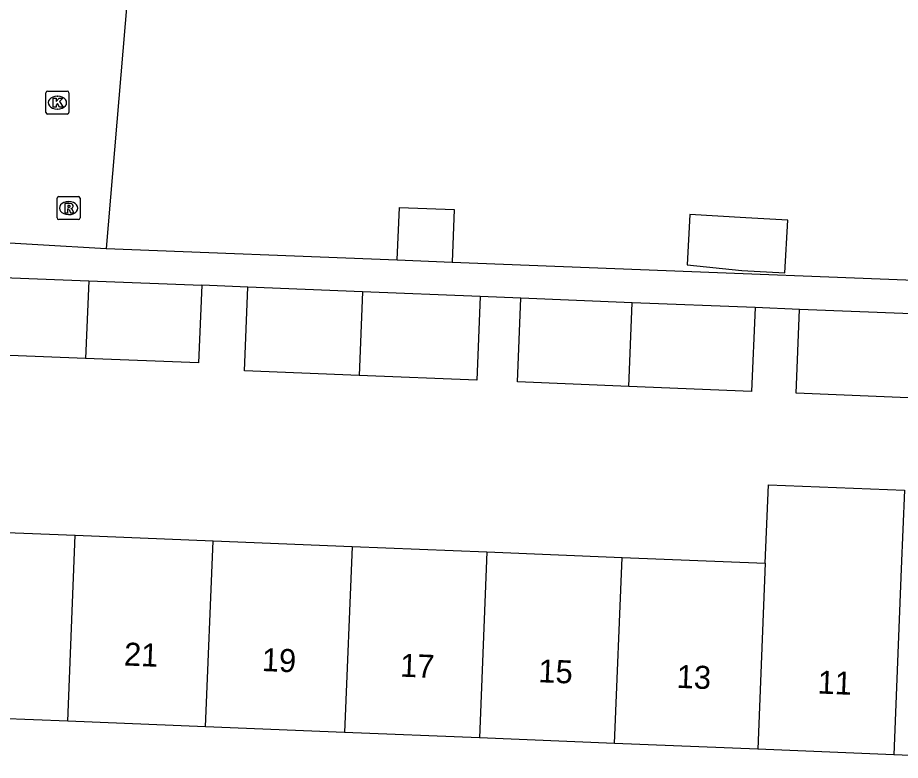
# Model space of a CAD drawing. Extents: x 161355 to 162026, y 386504 to 387459.
# Drawn here: x 161432.85 to 161471.21, y 386887.06 to 386919.31 of the extents above; entities that cross this region are included whole.
import ezdxf

# ---------------------------------------------------------------- set-up
doc = ezdxf.new("R2010")
doc.units = 0
for name, color, linetype in [('IMGEO_Kolk', 7, 'Continuous'), ('IMGEO_Pand', 7, 'Continuous'), ('IMGEO_Pand_nummerreeks', 7, 'Continuous'), ('IMGEO_Rijbaan_lokaal_open', 7, 'Continuous'), ('IMGEO_Rioolput', 7, 'Continuous'), ('IMGEO_Voetpad_open', 7, 'Continuous')]:
    doc.layers.add(name, color=color, linetype=linetype)

msp = doc.modelspace()

# ---------------------------------------------------------------- linework, layer by layer
at = {"layer": 'IMGEO_Kolk'}
for p, q in [((161434.077, 386915.196), (161434.077, 386916.048)), ((161434.152, 386916.122), (161435.004, 386916.122)), ((161435.078, 386916.048), (161435.078, 386915.196)), ((161434.565, 386915.902), (161434.59, 386915.902)), ((161434.588, 386915.342), (161434.563, 386915.342)), ((161435.004, 386915.122), (161434.152, 386915.122))]:
    msp.add_line(p, q, dxfattribs=at)
for points in [[(161434.077, 386915.196), (161434.077, 386916.048)], [(161434.152, 386916.122), (161435.004, 386916.122)], [(161435.078, 386916.048), (161435.078, 386915.196)], [(161434.398, 386915.822), (161434.521, 386915.822), (161434.521, 386915.671), (161434.651, 386915.822), (161434.815, 386915.822), (161434.669, 386915.671), (161434.822, 386915.422), (161434.67, 386915.422), (161434.585, 386915.586), (161434.521, 386915.519), (161434.521, 386915.422), (161434.398, 386915.422), (161434.398, 386915.822)], [(161435.004, 386915.122), (161434.152, 386915.122)]]:
    msp.add_lwpolyline(points, dxfattribs=at)
for centre, start, end in [((161434.154, 386916.046), 91.552, 178.448), ((161434.154, 386916.046), 91.552, 178.448), ((161435.002, 386916.046), 1.552, 88.448), ((161435.002, 386916.046), 1.552, 88.448), ((161434.154, 386915.198), 181.552, 268.448), ((161434.154, 386915.198), 181.552, 268.448), ((161435.002, 386915.198), 271.552, 358.448), ((161435.002, 386915.198), 271.552, 358.448)]:
    msp.add_arc(centre, 0.0765, start, end, dxfattribs=at)
for centre, major_axis, ratio, start_param, end_param in [((161434.564, 386915.622), (-0.387, 0.002), 0.722429, 4.712389, 7.853982), ((161434.589, 386915.622), (-0.39, 0.002), 0.717154, 1.570796, 4.712389)]:
    msp.add_ellipse(centre, major_axis=major_axis, ratio=ratio, start_param=start_param, end_param=end_param, dxfattribs=at)
at = {"layer": 'IMGEO_Pand'}
for points in [[(161449.342, 386908.791), (161449.437, 386911.072), (161451.82, 386910.976), (161451.735, 386908.697)], [(161464.498, 386910.616), (161462.064, 386910.76), (161461.946, 386908.58), (161464.312, 386908.335), (161466.189, 386908.233), (161466.312, 386910.518), (161464.498, 386910.616)], [(161449.342, 386908.791), (161451.735, 386908.697)], [(161427.629, 386905.199), (161427.748, 386908.207), (161435.936, 386907.883)], [(161435.936, 386907.883), (161435.8, 386904.511)], [(161440.848, 386907.689), (161440.715, 386904.316), (161435.8, 386904.511)], [(161435.936, 386907.883), (161440.848, 386907.689)], [(161447.683, 386903.769), (161442.709, 386903.97), (161442.855, 386907.608)], [(161447.83, 386907.407), (161442.855, 386907.608)], [(161447.83, 386907.407), (161447.683, 386903.769)], [(161452.954, 386907.2), (161452.808, 386903.562), (161447.683, 386903.769)], [(161452.954, 386907.2), (161447.83, 386907.407)], [(161459.412, 386903.296), (161454.569, 386903.491), (161454.716, 386907.129)], [(161459.559, 386906.934), (161454.716, 386907.129)], [(161459.412, 386903.296), (161459.559, 386906.934)], [(161464.89, 386906.719), (161459.559, 386906.934)], [(161464.89, 386906.719), (161464.744, 386903.08), (161459.412, 386903.296)], [(161471.546, 386902.806), (161466.677, 386903.003), (161466.823, 386906.641)], [(161471.693, 386906.444), (161466.823, 386906.641)], [(161435.8, 386904.511), (161431.026, 386904.7), (161431.041, 386905.064), (161427.629, 386905.199)], [(161465.338, 386895.62), (161465.476, 386899.024), (161471.383, 386898.785), (161471.245, 386895.381)], [(161435.027, 386888.756), (161429.052, 386888.998), (161429.254, 386893.994), (161429.379, 386897.074), (161435.354, 386896.832)], [(161435.027, 386888.756), (161435.354, 386896.832)], [(161435.354, 386896.832), (161441.339, 386896.59)], [(161441.012, 386888.514), (161441.339, 386896.59)], [(161441.339, 386896.59), (161447.382, 386896.346)], [(161447.382, 386896.346), (161447.055, 386888.27)], [(161447.382, 386896.346), (161453.24, 386896.109)], [(161453.24, 386896.109), (161452.913, 386888.033)], [(161453.24, 386896.109), (161459.111, 386895.871)], [(161458.784, 386887.795), (161459.111, 386895.871)], [(161459.111, 386895.871), (161465.338, 386895.62)], [(161465.338, 386895.62), (161465.011, 386887.543)], [(161471.245, 386895.381), (161470.918, 386887.304)], [(161441.012, 386888.514), (161435.027, 386888.756)], [(161447.055, 386888.27), (161441.012, 386888.514)], [(161452.913, 386888.033), (161447.055, 386888.27)], [(161458.784, 386887.795), (161452.913, 386888.033)], [(161465.011, 386887.543), (161458.784, 386887.795)], [(161470.918, 386887.304), (161465.011, 386887.543)], [(161477.013, 386887.058), (161470.918, 386887.304)]]:
    msp.add_lwpolyline(points, dxfattribs=at)
at = {"layer": 'IMGEO_Rijbaan_lokaal_open'}
for points in [[(161437.887, 386923.357), (161436.696, 386909.288)], [(161430.74, 386909.638), (161436.696, 386909.288)]]:
    msp.add_lwpolyline(points, dxfattribs=at)
at = {"layer": 'IMGEO_Rioolput'}
for p, q in [((161434.563, 386910.616), (161434.563, 386911.468)), ((161434.638, 386911.542), (161435.49, 386911.542)), ((161435.564, 386911.468), (161435.564, 386910.616)), ((161435.051, 386911.322), (161435.076, 386911.322)), ((161435.074, 386910.762), (161435.049, 386910.762)), ((161435.49, 386910.542), (161434.638, 386910.542))]:
    msp.add_line(p, q, dxfattribs=at)
for points in [[(161434.563, 386910.616), (161434.563, 386911.468)], [(161434.638, 386911.542), (161435.49, 386911.542)], [(161435.564, 386911.468), (161435.564, 386910.616)], [(161435.152, 386911.24), (161434.9, 386911.242), (161434.9, 386910.842)], [(161435.078, 386911.161), (161435.024, 386911.161), (161435.024, 386911.08)], [(161435.024, 386911.08), (161435.076, 386911.08)], [(161434.9, 386910.842), (161435.024, 386910.842), (161435.024, 386911.004), (161435.035, 386911.004)], [(161435.082, 386910.975), (161435.153, 386910.842), (161435.293, 386910.842), (161435.228, 386910.968)], [(161435.49, 386910.542), (161434.638, 386910.542)]]:
    msp.add_lwpolyline(points, dxfattribs=at)
for centre, radius, start, end in [((161434.64, 386911.466), 0.0765, 91.552, 178.448), ((161434.64, 386911.466), 0.0765, 91.552, 178.448), ((161435.488, 386911.466), 0.0765, 1.552, 88.448), ((161435.488, 386911.466), 0.0765, 1.552, 88.448), ((161435.06, 386911.269), 0.19, 274.7715, 282.9687), ((161435.084, 386911.065), 0.0964, 77.0061, 93.1865), ((161435.098, 386911.122), 0.0378, 276.6634, 79.6772), ((161435.151, 386911.13), 0.109, 350.3612, 89.416), ((161435.149, 386911.13), 0.112, 277.5842, 350.9817), ((161435.034, 386910.951), 0.0533, 26.0293, 88.6989), ((161435.133, 386910.915), 0.108, 29.5134, 73.7905), ((161434.64, 386910.618), 0.0765, 181.552, 268.448), ((161434.64, 386910.618), 0.0765, 181.552, 268.448), ((161435.488, 386910.618), 0.0765, 271.552, 358.448), ((161435.488, 386910.618), 0.0765, 271.552, 358.448)]:
    msp.add_arc(centre, radius, start, end, dxfattribs=at)
for centre, major_axis, ratio, start_param, end_param in [((161435.05, 386911.042), (-0.387, 0.002), 0.722429, 4.712389, 7.853982), ((161435.075, 386911.042), (-0.39, 0.002), 0.717154, 1.570796, 4.712389)]:
    msp.add_ellipse(centre, major_axis=major_axis, ratio=ratio, start_param=start_param, end_param=end_param, dxfattribs=at)
at = {"layer": 'IMGEO_Voetpad_open'}
for points in [[(161436.696, 386909.288), (161449.342, 386908.791)], [(161451.735, 386908.697), (161480.737, 386907.558), (161483.52, 386907.448), (161489.588, 386907.21), (161492.732, 386907.086), (161496.053, 386906.956)], [(161442.855, 386907.608), (161440.848, 386907.689)], [(161454.716, 386907.129), (161452.954, 386907.2)], [(161466.823, 386906.641), (161464.89, 386906.719)]]:
    msp.add_lwpolyline(points, dxfattribs=at)

# ---------------------------------------------------------------- texts
at = {"layer": 'IMGEO_Pand_nummerreeks'}
for s, rotation, p in [('21', 357.6839, (161437.456, 386891.18)), ('19', 357.6838, (161443.444, 386890.938)), ('17', 357.6839, (161449.454, 386890.695)), ('15', 357.6839, (161455.464, 386890.452)), ('13', 357.6838, (161461.474, 386890.209)), ('11', 357.6853, (161467.598, 386889.962))]:
    msp.add_text(s, height=1, rotation=rotation, dxfattribs=at).set_placement(p)

doc.saveas('drawing.dxf')
